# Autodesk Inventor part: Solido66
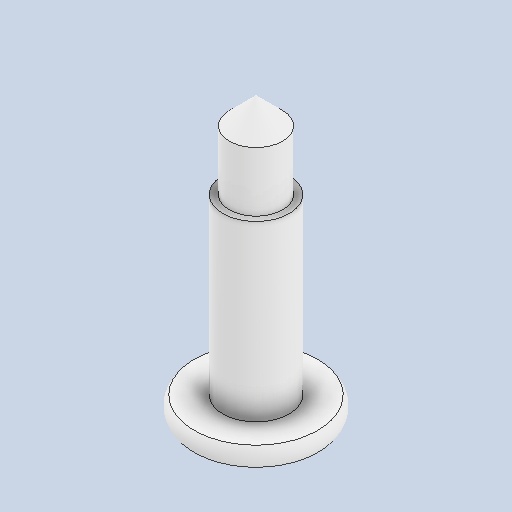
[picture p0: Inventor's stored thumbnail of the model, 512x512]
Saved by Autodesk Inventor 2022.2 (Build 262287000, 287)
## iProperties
Created: 2024-10
Part Number: Solido66
Material: Generico
Document SubType Name: Modeling
Designer: 18907419
Density: 1 g/cm^3
Appearance: Default
Author: 18907419
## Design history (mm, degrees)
feature "Solido66"
node "Solido1"
